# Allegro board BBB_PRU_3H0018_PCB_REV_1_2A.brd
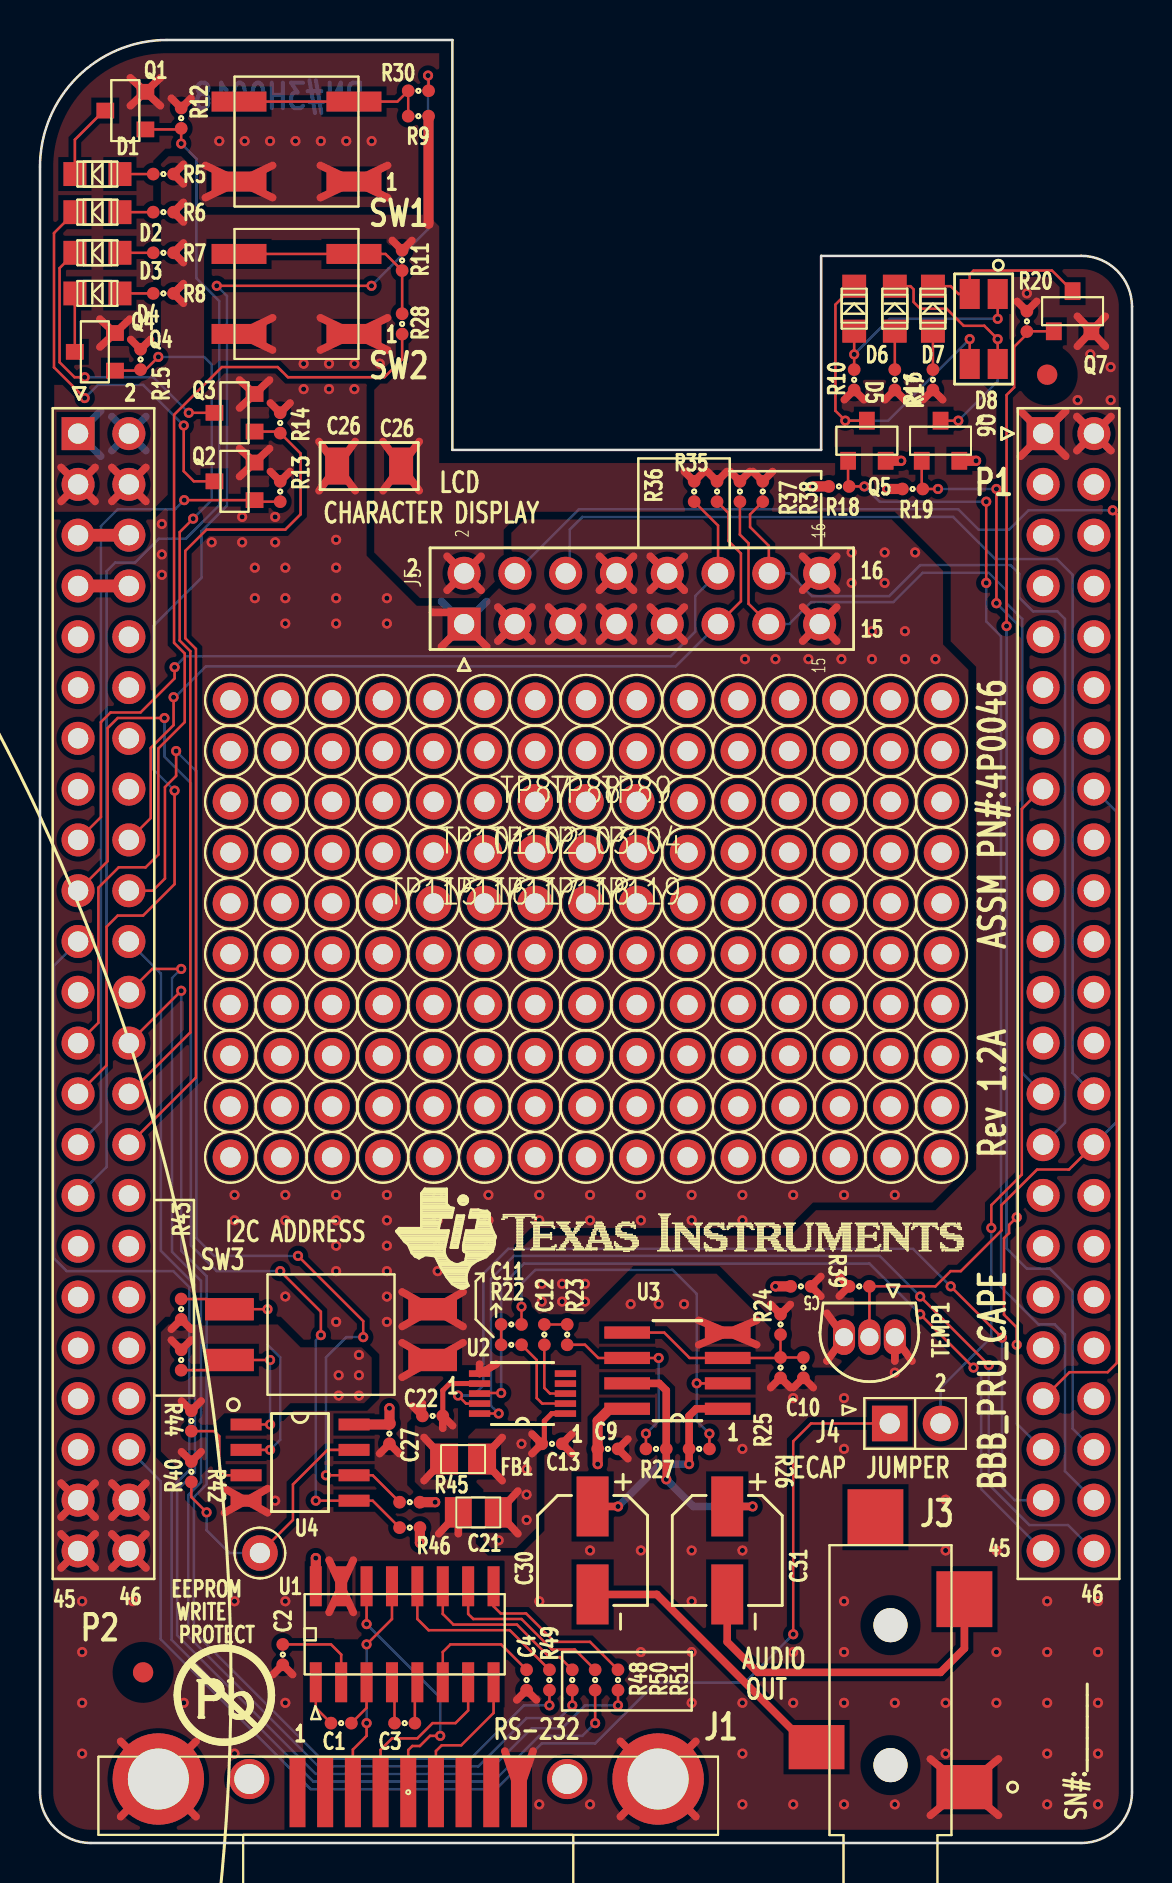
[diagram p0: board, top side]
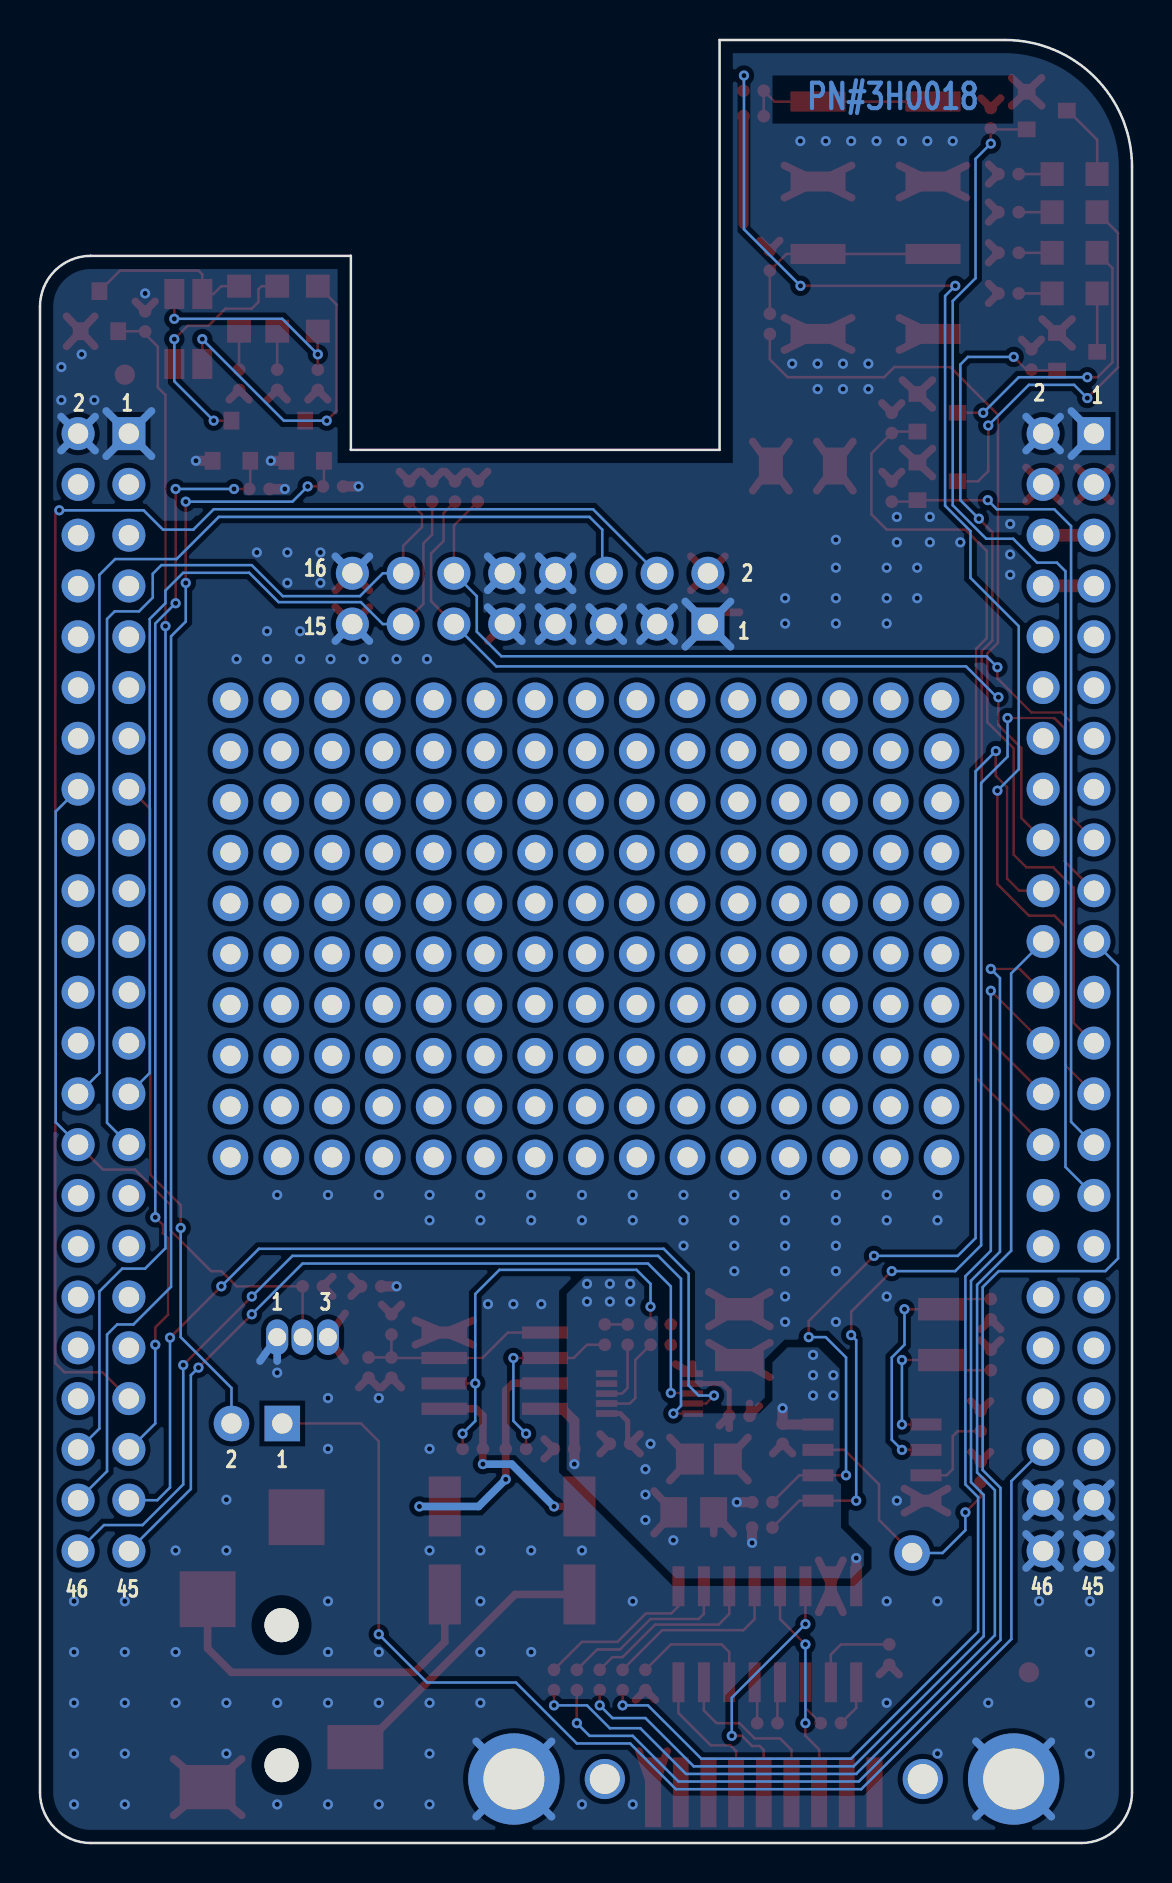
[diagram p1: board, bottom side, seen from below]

Outline 54.61 x 90.17 mm; copper layers: TOP, BOTTOM. Coordinates in mm from the lower left corner of the outline.
Outline path: 0,83.82 arc(1.86,88.31) 6.35,90.17 20.62,90.17 20.62,69.67 39.07,69.67 39.07,79.38 52.07,79.38 arc(53.87,78.63) 54.61,76.84 54.61,2.54 arc(53.87,0.74) 52.07,0 2.54,0 arc(0.74,0.74) 0,2.54 0,83.82

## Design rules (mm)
net group PWR: nets VCC_3V3_AUDIO VCC_5V
nets with their own width: min track width 0.381; nets N10952938 N10953743 N10962161 N11005950

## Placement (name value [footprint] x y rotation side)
C1  0.1uF  [SM-7351-CAP-0402]  15.06 5.99 0 top
C2  0.1uF  [SM-7351-CAP-0402]  12.14 9.42 270 top
C3  0.1uF  [SM-7351-CAP-0402]  18.24 5.99 0 top
C4  0.1uF  [SM-7351-CAP-0402]  24.33 8.15 270 top
C5  0.1uF  [SM-7351-CAP-0402]  38.05 27.84 180 top
C9  0.1uF  [SM-7351-CAP-0402]  28.4 19.71 0 top
C10  1uF  [SM-7351-CAP-0402]  38.18 23.77 90 top
C11  2.2uF, 10V  [SM-7351-CAP-0402]  23.57 24.92 180 top
C12  2.2uF, 10V  [SM-7351-CAP-0402]  25.22 25.43 90 top
C13  0.1uF  [SM-7351-CAP-0402]  25.6 19.96 0 top
C21  10uF  [SM-7351-CAP-0805]  21.92 16.54 180 top
C22  0.1uF  [SM-7351-CAP-0402]  19.63 21.36 180 top
C26  47uF  [SM-7351-CAP-1206]  16.46 68.86 0 top
C27  0.1uF  [SM-7351-CAP-0402]  17.48 20.47 270 top
C30  100uF, 6.3V  [CAP-ALUM-FS-D5XL5]  27.64 14.63 270 top
C31  100uF, 6.3V  [CAP-ALUM-FS-D5XL5]  34.37 14.63 270 top
D1  Blue LED  [SM_LED_0805]  2.87 83.46 180 top
D2  Green LED  [SM_LED_0805]  2.87 81.56 180 top
D3  Orange LED  [SM_LED_0805]  2.87 79.53 180 top
D4  Red LED  [SM_LED_0805]  2.87 77.5 180 top
D5  Blue LED  [SM_LED_0805]  40.72 76.73 90 top
D6  Green LED  [SM_LED_0805]  42.75 76.73 90 top
D7  Red LED  [SM_LED_0805]  44.65 76.73 90 top
D8  Red_Green_Yellow_LED  [LED-SM1210]  47.19 75.72 270 top
FB1  150OHM800mA  [SM-7351-IND-0805]  21.16 19.2 180 top
J1  Conn_DB9M  [NORCOMP_DB9M_SMD]  18.41 2.54 180 top
J3  3.5mm SJ3524  [SJ3524SMT4PIN]  46.48 2.79 270 top
J4  HEADER 2  [HEADER_2X1]  42.49 20.98 270 top
J5  HEADER 8x2 Female  [HDR2X8-335M]  21.21 60.96 90 top
NOREF  -  []  0 83.82 0 top
NOREF#2  -  []  52.07 0 90 top
NOREF#3  -  []  5.92 3.2 0 top
NOREF#4  -  [unnamed#2]  50.37 73.43 0 top
NOREF#5  -  []  21.98 21.48 0 top
NOREF#6  -  []  2.54 0 90 top
NOREF#7  -  []  20.62 90.17 0 top
NOREF#8  -  []  39.07 79.38 0 top
NOREF#9  -  []  9.22 7.39 0 top
NOREF#10  -  []  1.58 88.01 0 top
NOREF#11  -  []  -47.27 -78.56 0 top
NOREF#12  -  []  54.03 78.45 0 top
NOREF#13  -  [unnamed#2]  5.16 8.53 0 top
NOREF#14  -  []  0 83.82 0 top
P1  MALE HEADER 2x23  [HEADER23X2]  50.16 70.48 270 top
P2  MALE HEADER 2x23  [HEADER23X2]  1.9 70.48 270 top
Q1  BSS138  [SOT23-3]  4.27 86.64 90 top
Q2  BSS138  [SOT23-3]  9.73 68.1 90 top
Q3  BSS138  [SOT23-3]  9.73 71.53 90 top
Q4  BSS138  [SOT23-3]  2.74 74.57 90 top
Q5  BSS138  [SOT23-3]  41.35 70.13 0 top
Q6  BSS138  [SOT23-3]  45.03 70.13 0 top
Q7  BSS138  [SOT23-3]  51.64 76.61 0 top
R5  470  [SM-7351-RES-0402]  6.17 83.46 0 top
R6  68  [SM-7351-RES-0402]  6.17 81.56 0 top
R7  470  [SM-7351-RES-0402]  6.17 79.53 0 top
R8  300  [SM-7351-RES-0402]  6.17 77.5 0 top
R9  100K  [SM-7351-RES-0402]  18.92 86.36 0 top
R10  470  [SM-7351-RES-0402]  40.72 73.18 270 top
R11  100K  [SM-7351-RES-0402]  18.11 79.15 90 top
R12  100K  [SM-7351-RES-0402]  7.06 86.26 270 top
R13  100K  [SM-7351-RES-0402]  12.01 67.59 270 top
R14  100K  [SM-7351-RES-0402]  12.01 71.02 270 top
R15  100K  [SM-7351-RES-0402]  5.03 74.19 270 top
R16  68  [SM-7351-RES-0402]  42.75 73.18 270 top
R17  300  [SM-7351-RES-0402]  44.65 73.18 270 top
R18  100K  [SM-7351-RES-0402]  39.95 67.84 0 top
R19  100K  [SM-7351-RES-0402]  43.64 67.72 0 top
R20  100K  [SM-7351-RES-0402]  49.35 76.1 270 top
R22  3.9K  [SM-7351-RES-0402]  23.57 25.93 180 top
R23  3.9K  [SM-7351-RES-0402]  26.37 25.43 90 top
R24  100K  [SM-7351-RES-0402]  37.03 25.93 90 top
R25  100K  [SM-7351-RES-0402]  37.03 23.77 90 top
R26  1K  [SM-7351-RES-0402]  32.97 19.71 0 top
R27  1K  [SM-7351-RES-0402]  30.81 19.71 0 top
R28  100K  [SM-7351-RES-0402]  18.11 75.97 90 top
R30  100K  [SM-7351-RES-0402]  18.92 87.63 180 top
R35  100K  [SM-7351-RES-0402]  33.86 67.59 90 top
R36  100K  [SM-7351-RES-0402]  32.72 67.59 90 top
R37  100K  [SM-7351-RES-0402]  35 67.59 90 top
R38  100K  [SM-7351-RES-0402]  36.14 67.59 90 top
R39  4.7K  [SM-7351-RES-0402]  40.97 27.84 180 top
R40  100K  [SM-7351-RES-0402]  7.57 18.57 90 top
R42  4.7K  [SM-7351-RES-0402]  7.06 24.16 90 top
R43  4.7K  [SM-7351-RES-0402]  7.06 26.7 270 top
R44  4.7K  [SM-7351-RES-0402]  7.57 21.11 90 top
R45  4.7K  [SM-7351-RES-0402]  18.49 17.04 0 top
R46  4.7K  [SM-7351-RES-0402]  18.49 15.77 0 top
R48  0  [SM-7351-RES-0402]  26.62 8.15 270 top
R49  0  [SM-7351-RES-0402]  25.48 8.15 270 top
R50  0  [SM-7351-RES-0402]  27.76 8.15 270 top
R51  0  [SM-7351-RES-0402]  28.91 8.15 270 top
SW1  B3SL-1002P  [SW_B3SL-1022P]  12.83 85.09 0 top
SW2  B3SL-1002P  [SW_B3SL-1022P]  12.83 77.47 0 top
SW3  SW DIP-2  [SWDIP2_SMD]  18.36 24.16 180 top
TEMP1  MAX31820MCR  [TO-92-3P]  42.75 25.3 180 top
TP50  TP  [TH_TP_5002]  11 14.5 0 top
TP51  TP  [TH_TP_5002]  9.52 57.15 0 top
TP52  TP  [TH_TP_5002]  12.06 57.15 0 top
TP53  TP  [TH_TP_5002]  14.61 57.15 0 top
TP54  TP  [TH_TP_5002]  17.14 57.15 0 top
TP55  TP  [TH_TP_5002]  19.68 57.15 0 top
TP56  TP  [TH_TP_5002]  22.22 57.15 0 top
TP57  TP  [TH_TP_5002]  24.77 57.15 0 top
TP58  TP  [TH_TP_5002]  27.3 57.15 0 top
TP59  TP  [TH_TP_5002]  29.84 57.15 0 top
TP60  TP  [TH_TP_5002]  32.38 57.15 0 top
TP61  TP  [TH_TP_5002]  34.92 57.15 0 top
TP62  TP  [TH_TP_5002]  37.47 57.15 0 top
TP63  TP  [TH_TP_5002]  40 57.15 0 top
TP64  TP  [TH_TP_5002]  42.55 57.15 0 top
TP65  TP  [TH_TP_5002]  45.09 57.15 0 top
TP66  TP  [TH_TP_5002]  9.52 54.61 0 top
TP67  TP  [TH_TP_5002]  12.06 54.61 0 top
TP68  TP  [TH_TP_5002]  14.61 54.61 0 top
TP69  TP  [TH_TP_5002]  17.14 54.61 0 top
TP70  TP  [TH_TP_5002]  19.68 54.61 0 top
TP71  TP  [TH_TP_5002]  22.22 54.61 0 top
TP72  TP  [TH_TP_5002]  24.77 54.61 0 top
TP73  TP  [TH_TP_5002]  27.3 54.61 0 top
TP74  TP  [TH_TP_5002]  29.84 54.61 0 top
TP75  TP  [TH_TP_5002]  32.38 54.61 0 top
TP76  TP  [TH_TP_5002]  34.92 54.61 0 top
TP77  TP  [TH_TP_5002]  37.47 54.61 0 top
TP78  TP  [TH_TP_5002]  40 54.61 0 top
TP79  TP  [TH_TP_5002]  42.55 54.61 0 top
TP80  TP  [TH_TP_5002]  45.09 54.61 0 top
TP81  TP  [TH_TP_5002]  9.52 52.07 0 top
TP82  TP  [TH_TP_5002]  12.06 52.07 0 top
TP83  TP  [TH_TP_5002]  14.61 52.07 0 top
TP84  TP  [TH_TP_5002]  17.14 52.07 0 top
TP85  TP  [TH_TP_5002]  19.68 52.07 0 top
TP86  TP  [TH_TP_5002]  22.22 52.07 0 top
TP87  TP  [TH_TP_5002]  24.77 52.07 0 top
TP88  TP  [TH_TP_5002]  27.3 52.07 0 top
TP89  TP  [TH_TP_5002]  29.84 52.07 0 top
TP90  TP  [TH_TP_5002]  32.38 52.07 0 top
TP91  TP  [TH_TP_5002]  34.92 52.07 0 top
TP92  TP  [TH_TP_5002]  37.47 52.07 0 top
TP93  TP  [TH_TP_5002]  40 52.07 0 top
TP94  TP  [TH_TP_5002]  42.55 52.07 0 top
TP95  TP  [TH_TP_5002]  45.09 52.07 0 top
TP96  TP  [TH_TP_5002]  9.52 49.53 0 top
TP97  TP  [TH_TP_5002]  12.06 49.53 0 top
TP98  TP  [TH_TP_5002]  14.61 49.53 0 top
TP99  TP  [TH_TP_5002]  17.14 49.53 0 top
TP100  TP  [TH_TP_5002]  19.68 49.53 0 top
TP101  TP  [TH_TP_5002]  22.22 49.53 0 top
TP102  TP  [TH_TP_5002]  24.77 49.53 0 top
TP103  TP  [TH_TP_5002]  27.3 49.53 0 top
TP104  TP  [TH_TP_5002]  29.84 49.53 0 top
TP105  TP  [TH_TP_5002]  32.38 49.53 0 top
TP106  TP  [TH_TP_5002]  34.92 49.53 0 top
TP107  TP  [TH_TP_5002]  37.47 49.53 0 top
TP108  TP  [TH_TP_5002]  40 49.53 0 top
TP109  TP  [TH_TP_5002]  42.55 49.53 0 top
TP110  TP  [TH_TP_5002]  45.09 49.53 0 top
TP111  TP  [TH_TP_5002]  9.52 46.99 0 top
TP112  TP  [TH_TP_5002]  12.06 46.99 0 top
TP113  TP  [TH_TP_5002]  14.61 46.99 0 top
TP114  TP  [TH_TP_5002]  17.14 46.99 0 top
TP115  TP  [TH_TP_5002]  19.68 46.99 0 top
TP116  TP  [TH_TP_5002]  22.22 46.99 0 top
TP117  TP  [TH_TP_5002]  24.77 46.99 0 top
TP118  TP  [TH_TP_5002]  27.3 46.99 0 top
TP119  TP  [TH_TP_5002]  29.84 46.99 0 top
TP120  TP  [TH_TP_5002]  32.38 46.99 0 top
TP121  TP  [TH_TP_5002]  34.92 46.99 0 top
TP122  TP  [TH_TP_5002]  37.47 46.99 0 top
TP123  TP  [TH_TP_5002]  40 46.99 0 top
TP124  TP  [TH_TP_5002]  42.55 46.99 0 top
TP125  TP  [TH_TP_5002]  45.09 46.99 0 top
TP126  TP  [TH_TP_5002]  9.52 44.45 0 top
TP127  TP  [TH_TP_5002]  12.06 44.45 0 top
TP128  TP  [TH_TP_5002]  14.61 44.45 0 top
TP129  TP  [TH_TP_5002]  17.14 44.45 0 top
TP130  TP  [TH_TP_5002]  19.68 44.45 0 top
TP131  TP  [TH_TP_5002]  22.22 44.45 0 top
TP132  TP  [TH_TP_5002]  24.77 44.45 0 top
TP133  TP  [TH_TP_5002]  27.3 44.45 0 top
TP134  TP  [TH_TP_5002]  29.84 44.45 0 top
TP135  TP  [TH_TP_5002]  32.38 44.45 0 top
TP136  TP  [TH_TP_5002]  34.92 44.45 0 top
TP137  TP  [TH_TP_5002]  37.47 44.45 0 top
TP138  TP  [TH_TP_5002]  40 44.45 0 top
TP139  TP  [TH_TP_5002]  42.55 44.45 0 top
TP140  TP  [TH_TP_5002]  45.09 44.45 0 top
TP141  TP  [TH_TP_5002]  9.52 41.91 0 top
TP142  TP  [TH_TP_5002]  12.06 41.91 0 top
TP143  TP  [TH_TP_5002]  14.61 41.91 0 top
TP144  TP  [TH_TP_5002]  17.14 41.91 0 top
TP145  TP  [TH_TP_5002]  19.68 41.91 0 top
TP146  TP  [TH_TP_5002]  22.22 41.91 0 top
TP147  TP  [TH_TP_5002]  24.77 41.91 0 top
TP148  TP  [TH_TP_5002]  27.3 41.91 0 top
TP149  TP  [TH_TP_5002]  29.84 41.91 0 top
TP150  TP  [TH_TP_5002]  32.38 41.91 0 top
TP151  TP  [TH_TP_5002]  34.92 41.91 0 top
TP152  TP  [TH_TP_5002]  37.47 41.91 0 top
TP153  TP  [TH_TP_5002]  40 41.91 0 top
TP154  TP  [TH_TP_5002]  42.55 41.91 0 top
TP155  TP  [TH_TP_5002]  45.09 41.91 0 top
TP156  TP  [TH_TP_5002]  9.52 39.37 0 top
TP157  TP  [TH_TP_5002]  12.06 39.37 0 top
TP158  TP  [TH_TP_5002]  14.61 39.37 0 top
TP159  TP  [TH_TP_5002]  17.14 39.37 0 top
TP160  TP  [TH_TP_5002]  19.68 39.37 0 top
TP161  TP  [TH_TP_5002]  22.22 39.37 0 top
TP162  TP  [TH_TP_5002]  24.77 39.37 0 top
TP163  TP  [TH_TP_5002]  27.3 39.37 0 top
TP164  TP  [TH_TP_5002]  29.84 39.37 0 top
TP165  TP  [TH_TP_5002]  32.38 39.37 0 top
TP166  TP  [TH_TP_5002]  34.92 39.37 0 top
TP167  TP  [TH_TP_5002]  37.47 39.37 0 top
TP168  TP  [TH_TP_5002]  40 39.37 0 top
TP169  TP  [TH_TP_5002]  42.55 39.37 0 top
TP170  TP  [TH_TP_5002]  45.09 39.37 0 top
TP171  TP  [TH_TP_5002]  9.52 36.83 0 top
TP172  TP  [TH_TP_5002]  12.06 36.83 0 top
TP173  TP  [TH_TP_5002]  14.61 36.83 0 top
TP174  TP  [TH_TP_5002]  17.14 36.83 0 top
TP175  TP  [TH_TP_5002]  19.68 36.83 0 top
TP176  TP  [TH_TP_5002]  22.22 36.83 0 top
TP177  TP  [TH_TP_5002]  24.77 36.83 0 top
TP178  TP  [TH_TP_5002]  27.3 36.83 0 top
TP179  TP  [TH_TP_5002]  29.84 36.83 0 top
TP180  TP  [TH_TP_5002]  32.38 36.83 0 top
TP181  TP  [TH_TP_5002]  34.92 36.83 0 top
TP182  TP  [TH_TP_5002]  37.47 36.83 0 top
TP183  TP  [TH_TP_5002]  40 36.83 0 top
TP184  TP  [TH_TP_5002]  42.55 36.83 0 top
TP185  TP  [TH_TP_5002]  45.09 36.83 0 top
TP186  TP  [TH_TP_5002]  9.52 34.29 0 top
TP187  TP  [TH_TP_5002]  12.06 34.29 0 top
TP188  TP  [TH_TP_5002]  14.61 34.29 0 top
TP189  TP  [TH_TP_5002]  17.14 34.29 0 top
TP190  TP  [TH_TP_5002]  19.68 34.29 0 top
TP191  TP  [TH_TP_5002]  22.22 34.29 0 top
TP192  TP  [TH_TP_5002]  24.77 34.29 0 top
TP193  TP  [TH_TP_5002]  27.3 34.29 0 top
TP194  TP  [TH_TP_5002]  29.84 34.29 0 top
TP195  TP  [TH_TP_5002]  32.38 34.29 0 top
TP196  TP  [TH_TP_5002]  34.92 34.29 0 top
TP197  TP  [TH_TP_5002]  37.47 34.29 0 top
TP198  TP  [TH_TP_5002]  40 34.29 0 top
TP199  TP  [TH_TP_5002]  42.55 34.29 0 top
TP200  TP  [TH_TP_5002]  45.09 34.29 0 top
U1  MAX3232E  [U_16_D]  18.24 10.44 0 top
U2  DAC082S085  [MUB10A-L]  24.13 22.48 180 top
U3  LM4808  [M08A-M]  31.88 23.62 180 top
U4  CAT24C256W  [SOIC8_MC]  13 19.02 0 top

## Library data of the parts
C1 C3 C9 C13 C22 C27 = 1C_0.1uFCapacitor16V10%0402
C2 C4 C5 = 1C_0.1uFCapacitor16V10%0402: Tolerance: TOLERANCE; User Part Number: USERPART#
C10 = 1C_1uFCapacitor10V10%0402
C11 C12 = 1C_2.2uFCapacitor10V20%smd0402
C21 = 1C_10uFCapacitor16V10%0805
C26 = 1C_47uFCapacitor16V20%1206
C30 C31 = 1C_100uFCapacitor6.3V20%ElecAl
D1 D5 = 1F_LED_Blue
D2 D6 = 1F_LED_Green
D3 = 1F_LED_Orange
D4 D7 = 1F_LED_Red
D8 = 1F_LED_Tricolor_RedGreenYellow
FB1 = 1L_FerBead_180ohm200mA
J1 = Conn_DSUB9M
J3 = 2C_Conn_3.5mm_SJ3524SMT
J4 = 2H_Header_2x1
J5 = 2H_Header8x2pin_female
P1 P2 = HDR_46_F_2_0.1_0.1
Q1-Q7 = 1Q_MOSFET_NChan_BSS138
R5 R7 R10 = 1R_470OhmResistor1/16W1%0402
R6 R16 = 1R_68ohm1/16W5%smd0402
R8 R17 = 1R_300ohm1/16W5%smd0402
R9 R11-R15 R18-R20 R24 R25 R28 R30 R35-R38 R40 = 1R_100KOhmResistor1/16W0402
R22 R23 = 1R_3.9Kohm1/16W1%smd0402
R26 R27 = 1R_1KOhmResistor1/16W0402
R39 R42-R46 = 1R_4.7KOhmResistor1/16W0402
R48-R51 = 1R_ZeroOhmResistor1/16W0402
SW1 SW2 = 2W_Switch_PushbuttonsmdNOtall
SW3 = SW DIP-2
TEMP1 = 1A_MAX31820MCR
TP50-TP200 = 2H_TestPointThroughHole
U1 = 1A_MAX3232E
U2 = 1A_DAC082S085
U3 = 1A_LM4808
U4 = 1A_CAT24C256W

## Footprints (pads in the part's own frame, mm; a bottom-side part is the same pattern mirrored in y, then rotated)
CAP-ALUM-FS-D5XL5
  rect 3x1.6 smd: 1(-2.2,0) 2(2.2,0)
HDR2X8-335M
  rect 1.651x1.651 hole 1.016: 1(0,0)
  round 1.651 hole 1.016: 2(2.54,0) 3(0,-2.54) 4(2.54,-2.54) 5(0,-5.08) 6(2.54,-5.08) 7(0,-7.62) 8(2.54,-7.62) 9(0,-10.16) 10(2.54,-10.16) 11(0,-12.7) 12(2.54,-12.7) 13(0,-15.24) 14(2.54,-15.24) 15(0,-17.78) 16(2.54,-17.78)
HEADER23X2
  rect 1.651x1.651 hole 1.016: 1(0,0)
  round 1.651 hole 1.016: 2(0,2.54) 3(2.54,0) 4(2.54,2.54) 5(5.08,0) 6(5.08,2.54) 7(7.62,0) 8(7.62,2.54) 9(10.16,0) 10(10.16,2.54) 11(12.7,0) 12(12.7,2.54) 13(15.24,0) 14(15.24,2.54) 15(17.78,0) 16(17.78,2.54) 17(20.32,0) 18(20.32,2.54) 19(22.86,0) 20(22.86,2.54) 21(25.4,0) 22(25.4,2.54) 23(27.94,0) 24(27.94,2.54) 25(30.48,0) 26(30.48,2.54) 27(33.02,0) 28(33.02,2.54) 29(35.56,0) 30(35.56,2.54) 31(38.1,0) 32(38.1,2.54) 33(40.64,0) 34(40.64,2.54) 35(43.18,0) 36(43.18,2.54) 37(45.72,0) 38(45.72,2.54) 39(48.26,0) 40(48.26,2.54) 41(50.8,0) 42(50.8,2.54) 43(53.34,0) 44(53.34,2.54) 45(55.88,0) 46(55.88,2.54)
HEADER_2X1
  rect 1.778x1.778 hole 1.016: 1(0,0)
  round 1.778 hole 1.016: 2(0,2.54)
LED-SM1210
  rect 1.5x1 smd: 1(-1.75,0.7) 2(-1.75,-0.7) 3(1.75,0.7) 4(1.75,-0.7)
M08A-M
  rect 2.286x0.61 smd: 1(-2.515,1.905) 2(-2.515,0.635) 3(-2.515,-0.635) 4(-2.515,-1.905) 5(2.515,-1.905) 6(2.515,-0.635) 7(2.515,0.635) 8(2.515,1.905)
MUB10A-L
  rect 1.067x0.33 smd: 1(-2.146,1) 2(-2.146,0.5) 3(-2.146,0) 4(-2.146,-0.5) 5(-2.146,-1) 6(2.146,-1) 7(2.146,-0.5) 8(2.146,0) 9(2.146,0.5) 10(2.146,1)
NORCOMP_DB9M_SMD
  round 2.007 hole 1.499 unplated: (-7.95,-0.66) (7.95,-0.66)
  rect 0.8x3.5 smd: 1(5.537,0) 2(2.769,0) 3(0,0) 4(-2.769,0) 5(-5.537,0) 6(4.153,0) 7(1.384,0) 8(-1.384,0) 9(-4.153,0)
  round 4.572 hole 3.048: 10(-12.497,-0.66) 11(12.497,-0.66)
SJ3524SMT4PIN
  round 1.702 hole 1.702 unplated: (-8.1,-3.95) (-1.1,-3.95)
  rect 2.21x2.794 smd: 1(0,-0.253) 3(-2,-7.647)
  rect 2.794x2.794 smd: 2(-9.4,-0.253) 10(-13.5,-4.703)
SM-7351-CAP-0402
  round 0.635 smd: 1(-0.508,0) 2(0.508,0)
SM-7351-CAP-0805
  rect 1.346x1.524 smd: 1(-1,0) 2(1,0)
SM-7351-CAP-1206
  rect 1.2x1.85 smd: 1(1.6,0) 2(-1.6,0)
SM-7351-IND-0805
  rect 1.397x1.549 smd: 1(-0.95,0) 2(0.95,0)
SM-7351-RES-0402
  round 0.635 smd: 1(-0.508,0) 2(0.508,0)
SM_LED_0805
  rect 1.15x1.194 smd: 1(1.125,0) 2(-1.125,0)
SOIC8_MC
  rect 1.55x0.6 smd: 1(-2.7,1.905) 2(-2.7,0.635) 3(-2.7,-0.635) 4(-2.7,-1.905) 5(2.7,-1.905) 6(2.7,-0.635) 7(2.7,0.635) 8(2.7,1.905)
SOT23-3
  rect 0.787x0.889 smd: D(0,1.003) G(-0.94,-1.003) S(0.94,-1.003)
SW_B3SL-1022P
  rect 2.75x1 smd: 1(2.875,-2) 2(-2.875,-2) 3(2.875,2) 4(-2.875,2)
SWDIP2_SMD
  rect 2.438x1.118 smd: 1(-1.27,0) 2(-1.27,-2.54) 3(8.89,-2.54) 4(8.89,0)
TH_TP_5002
  round 1.778 hole 1.016: 1(0,0)
TO-92-3P
  oval 1.103x1.778 hole 0.9: 1(0,0) 2(1.27,0) 3(2.54,0)
U_16_D
  rect 0.6x2 smd: 1(-4.445,-2.4) 2(-3.175,-2.4) 3(-1.905,-2.4) 4(-0.635,-2.4) 5(0.635,-2.4) 6(1.905,-2.4) 7(3.175,-2.4) 8(4.445,-2.4) 9(4.445,2.4) 10(3.175,2.4) 11(1.905,2.4) 12(0.635,2.4) 13(-0.635,2.4) 14(-1.905,2.4) 15(-3.175,2.4) 16(-4.445,2.4)
unnamed#2
  round 1.016 smd: 1(0,0)

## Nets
DGND: C2.2 C4.2 C5.2 C9.2 C10.1 C13.2 C21.2 C22.2 C26.2 C27.2 J1.5 J1.10 J1.11 J3.1(P1) J5.1 J5.3 J5.5 J5.7 J5.8 J5.9 J5.10 J5.15 J5.16 P1.1 P1.2(26) P2.1 P2.2(26) P2.43(22) P2.44(47) P2.45(23) P2.46(48) Q1.S(SOURCE) Q2.S(SOURCE) Q3.S(SOURCE) Q4.S(SOURCE) Q5.S(SOURCE) Q6.S(SOURCE) Q7.S(SOURCE) R12.1(P1) R13.1(P1) R14.1(P1) R15.1(P1) R18.1(P1) R19.1(P1) R20.1(P1) R25.1(P1) SW1.1 SW1.2 SW2.1 SW2.2 SW3.1(A1) SW3.2(A2) TEMP1.1(GND) U1.15(GND) U2.6(GND) U3.4(GND) U4.4(VSS)
VCC_3V3_AUDIO: C22.1 FB1.2 U2.7(VREFIN)
VCC_3V3C: C5.1 C9.1 C13.1 C21.1 C26.1 C27.1 FB1.1 J5.2 P2.3(2) P2.4(27) R5.2(P2) R6.2(P2) R7.2(P2) R8.2(P2) R9.2(P2) R10.2(P2) R11.2(P2) R16.2(P2) R17.2(P2) R24.2(P2) R35.2(P2) R36.2(P2) R37.2(P2) R38.2(P2) R39.2(P2) R40.2(P2) R42.2(P2) R43.2(P2) R44.2(P2) R45.2(P2) R46.2(P2) TEMP1.3(VDD) U1.16(VCC) U2.1(VA) U3.8(VDD) U4.8(VCC)
VCC_5V: P2.5(3) P2.6(28)
I2C2_SCL: P2.20(35) R45.1(P1) U4.6(SCL)
I2C2_SDA: P2.19(10) R46.1(P1) U4.5(SDA)
PR1_ECAP0_IN_PWM0_OUT: J4.1 P2.42(46)
PR1_PRU0_GPI5: P2.27(14) R30.1(P1)
PR1_PRU0_GPI7: P2.25(13) R28.1(P1)
PR1_PRU0_GPI14: P1.16(33) P1.30(40) R39.1(P1) TEMP1.2(DQ)
PR1_PRU0_GPI15: J4.2 P1.15(8)
PR1_PRU0_GPO0: P2.31(16) Q1.G(GATE) R12.2(P2)
PR1_PRU0_GPO1: P2.29(15) Q2.G(GATE) R13.2(P2)
PR1_PRU0_GPO2: P2.30(40) Q3.G(GATE) R14.2(P2)
PR1_PRU0_GPO3: P2.28(39) Q4.G(GATE) R15.2(P2)
PR1_PRU1_GPO0: P1.45(23) U2.8(DIN)
PR1_PRU1_GPO1: P1.46(48) U2.10(SCLK)
PR1_PRU1_GPO2: P1.43(22) U2.9(SYNCN)
PR1_PRU1_GPO3: P1.44(47) Q5.G(GATE) R18.2(P2)
PR1_PRU1_GPO4: P1.41(21) Q6.G(GATE) R19.2(P2)
PR1_PRU1_GPO5: P1.42(46) Q7.G(GATE) R20.2(P2)
PR1_PRU_EDIO_DATA_OUT0: J5.11 P2.18(34) R35.1(P1)
PR1_PRU_EDIO_DATA_OUT1: J5.12 P2.17(9) R36.1(P1)
PR1_PRU_EDIO_DATA_OUT2: J5.13 P1.27(14) R37.1(P1)
PR1_PRU_EDIO_DATA_OUT3: J5.14 P1.29(15) R38.1(P1)
PR1_PRU_EDIO_DATA_OUT4: J5.6 P1.28(39)
PR1_PRU_EDIO_DATA_OUT6: J5.4 P1.39(20)
PR1_UART0_CTS: P2.22(36) R51.2(P2)
PR1_UART0_RTS: P2.21(11) R50.2(P2)
PR1_UART0_RXD: P2.26(38) R49.2(P2)
PR1_UART0_TXD: P2.24(37) R48.2(P2)
SYS_5V: P2.7(4) P2.8(29)
N10940793: J1.3 U1.14(DOUT1)
N10940805: J1.7 U1.7(DOUT2)
N10940817: J1.2 U1.13(RIN1)
N10940821: J1.8 U1.8(RIN2)
N10940859: C2.1 U1.2(V+)
N10940889: C4.1 U1.6(V-)
N10940931: C1.1 U1.1(C1+)
N10940935: C1.2 U1.3(C1-)
N10940955: C3.1 U1.4(C2+)
N10940959: C3.2 U1.5(C2-)
N10941007: R51.1(P1) U1.9(ROUT2)
N10941037: R48.1(P1) U1.11(DIN1)
N10941057: R50.1(P1) U1.10(DIN2)
N10941079: R49.1(P1) U1.12(ROUT1)
N10944684: D1.1(CATHODE) Q1.D(DRAIN)
N10944706: D2.1(CATHODE) Q2.D(DRAIN)
N10944710: D3.1(CATHODE) Q3.D(DRAIN)
N10944714: D4.1(CATHODE) Q4.D(DRAIN)
N10944926: R9.1(P1) R30.2(P2) SW1.3 SW1.4
N10945010: R11.1(P1) R28.2(P2) SW2.3 SW2.4
N10952704: R23.1(P1) R27.1(P1) U3.6(INB-)
N10952708: R22.1(P1) R26.2(P2) U3.2(INA-)
N10952712: C11.2 R22.2(P2)
N10952716: C11.1 U2.2(VOUTA)
N10952728: C12.2 R23.2(P2)
N10952732: C12.1 U2.3(VOUTB)
N10952860: C10.2 R24.1(P1) R25.2(P2) U3.3(INA+) U3.5(INB+)
N10952938: C30.1(POS) R26.1(P1) U3.1(OUTA)
N10953743: C31.2(NEG) J3.2(P2)
N10962161: C31.1(POS) R27.2(P2) U3.7(OUTB)
N10987134: R42.1(P1) SW3.4(B1) U4.1(A0)
N10987138: R43.1(P1) SW3.3(B2) U4.2(A1)
N10987943: R40.1(P1) TP50.1 U4.7(WP)
N10988256: R44.1(P1) U4.3(A2)
N11005950: C30.2(NEG) J3.3(P3)
N11019823: D5.2(ANODE) D8.1(A) R10.1(P1)
N11021666: D6.1(CATHODE) D8.3(G) Q6.D(DRAIN)
N11021673: D7.1(CATHODE) D8.2(R) Q7.D(DRAIN)
N11030938: D5.1(CATHODE) D8.4(Y) Q5.D(DRAIN)
N109444080: D1.2(ANODE) R5.1(P1)
N109444240: D2.2(ANODE) R6.1(P1)
N109444400: D3.2(ANODE) R7.1(P1)
N109444560: D4.2(ANODE) R8.1(P1)
N110315370: D6.2(ANODE) R16.1(P1)
N110319930: D7.2(ANODE) R17.1(P1)

Pads without a net: J1 1 4 6 9; J3 10; NOREF#4 1; NOREF#13 1; P1 3 4 5 6 7 8 9 10 11 12 13 14 17 18 19 20 21 22 23 24 25 26 31 32 33 34 35 36 37 38 40; P2 9 10 11 12 13 14 15 16 23 32 33 34 35 36 37 38 39 40 41; TP51 1; TP52 1; TP53 1; TP54 1; TP55 1; TP56 1; TP57 1; TP58 1; TP59 1; TP60 1; TP61 1; TP62 1; TP63 1; TP64 1; TP65 1; TP66 1; TP67 1; TP68 1; TP69 1; TP70 1; TP71 1; TP72 1; TP73 1; TP74 1; TP75 1; TP76 1; TP77 1; TP78 1; TP79 1; TP80 1; TP81 1; TP82 1; TP83 1; TP84 1; TP85 1; TP86 1; TP87 1; TP88 1; TP89 1; TP90 1; TP91 1; TP92 1; TP93 1; TP94 1; TP95 1; TP96 1; TP97 1; TP98 1; TP99 1; TP100 1; TP101 1; TP102 1; TP103 1; TP104 1; TP105 1; TP106 1; TP107 1; TP108 1; TP109 1; TP110 1; TP111 1; TP112 1; TP113 1; TP114 1; TP115 1; TP116 1; TP117 1; TP118 1; TP119 1; TP120 1; TP121 1; TP122 1; TP123 1; TP124 1; TP125 1; TP126 1; TP127 1; TP128 1; TP129 1; TP130 1; TP131 1; TP132 1; TP133 1; TP134 1; TP135 1; TP136 1; TP137 1; TP138 1; TP139 1; TP140 1; TP141 1; TP142 1; TP143 1; TP144 1; TP145 1; TP146 1; TP147 1; TP148 1; TP149 1; TP150 1; TP151 1; TP152 1; TP153 1; TP154 1; TP155 1; TP156 1; TP157 1; TP158 1; TP159 1; TP160 1; TP161 1; TP162 1; TP163 1; TP164 1; TP165 1; TP166 1; TP167 1; TP168 1; TP169 1; TP170 1; TP171 1; TP172 1; TP173 1; TP174 1; TP175 1; TP176 1; TP177 1; TP178 1; TP179 1; TP180 1; TP181 1; TP182 1; TP183 1; TP184 1; TP185 1; TP186 1; TP187 1; TP188 1; TP189 1; TP190 1; TP191 1; TP192 1; TP193 1; TP194 1; TP195 1; TP196 1; TP197 1; TP198 1; TP199 1; TP200 1; U2 4 5

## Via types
v1: diameter 0.508, hole 0.254, TOP to BOTTOM, 246 vias

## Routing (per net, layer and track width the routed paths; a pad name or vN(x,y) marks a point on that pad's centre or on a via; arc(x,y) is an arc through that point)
DGND: length 317.1
  TOP w0.381: 19.63,26.7 21.16,27.56 ; 19.63,26.7 18.11,25.83 ; 19.63,26.7 21.16,25.83 ; 19.63,26.7 18.11,27.56 ; 30.52,61.81 J5.9 ; J5.9 30.52,60.11 ; J5.9 32.22,60.11 ; J5.9 32.22,61.81 ; 12.51,68.59 12.01,68.1 11.52,68.59 ; J1.10 32.79,1.32 ; J1.10 29.03,1.32 ; J1.10 29.03,5.08 ; J1.10 32.79,5.08 ; 22.9,61.81 J5.3 ; J5.3 22.9,60.11 ; J5.3 24.6,61.81 ; J5.3 24.6,60.11 ; 20.92,15.47 C21.2 19.94,15.47 ; C26.2 15.76,67.63 ; C26.2 13.95,70.09 ; C26.2 13.95,67.63 ; C26.2 15.76,70.09 ; P2.45 2.76,13.75 ; P2.45 1.05,15.46 ; P2.45 1.05,13.75 ; P2.45 2.76,15.46 ; 18.11,25.02 SW3.1 ; SW3.1 21.16,25.02 ; SW3.1 18.11,23.29 ; 42.75,24.1 TEMP1.1 43.61,24.1 ; SW2.1 17.38,74.66 ; SW2.1 14.02,74.66 ; SW2.1 17.38,76.28 ; SW2.1 14.02,76.28 ; 3.59,13.75 P2.46 ; P2.46 5.3,13.75 ; P2.46 5.3,15.46 ; P2.46 3.59,15.46 ; 9.98,71.77 Q3.S ; Q3.S 11.48,73.17 ; Q3.S 9.98,73.17 ; 14.02,83.9 SW1.1 ; SW1.1 17.38,82.28 ; SW1.1 14.02,82.28 ; SW1.1 17.38,83.9 ; 51.88,76.35 Q7.S ; Q7.S 51.88,74.85 ; Q7.S 53.28,76.35 ; Q7.S 53.28,74.85 ; 25.44,60.11 J5.5 ; J5.5 27.14,60.11 ; J5.5 27.14,61.81 ; J5.5 25.44,61.81 ; J1.11 7.8,5.08 ; J1.11 7.8,1.32 ; J1.11 4.04,5.08 ; J1.11 4.04,1.32 ; 3,74.82 Q4.S ; Q4.S 3,76.21 ; Q4.S 4.5,76.21 ; P1.1 51.3,69.35 ; P1.1 51.3,71.62 ; P1.1 49.03,71.62 ; P1.1 49.03,69.35 ; 38.14,60.11 J5.15 ; J5.15 39.84,61.81 ; J5.15 38.14,61.81 ; J5.15 39.84,60.11 ; 48.86,77.1 R20.1 49.84,77.1 ; P2.44 5.3,18 ; P2.44 5.3,16.29 ; P2.44 3.59,18 ; P2.44 3.59,16.29 ; 12.63,8.42 C2.2 11.65,8.42 ; 23.25,4.6 J1.5 24.66,4.6 ; J5.10 32.22,64.35 ; J5.10 32.22,62.65 ; J5.10 30.52,62.65 ; J5.10 30.52,64.35 ; 9.22,17.72 U4.4 ; U4.4 9.22,16.51 ; U4.4 11.39,16.51 ; U4.4 11.39,17.72 ; 27.98,64.35 J5.8 ; J5.8 29.68,62.65 ; J5.8 29.68,64.35 ; J5.8 27.98,62.65 ; 11.52,72.02 R14.1 12.51,72.02 ; 21.98,23.95 U2.6 22.82,23.95 ; 4.52,86.88 Q1.S ; Q1.S 4.52,88.28 ; Q1.S 6.02,88.28 ; Q1.S 6.02,86.88 ; SW1.2 11.63,82.28 ; SW1.2 8.27,83.9 ; SW1.2 8.27,82.28 ; SW1.2 11.63,83.9 ; J5.1 22.34,59.83 ; J5.1 20.08,59.83 ; J5.1 20.63,61.54 19.64,61.54 19.63,61.55 ; 14.46,11.53 U1.15 ; U1.15 15.67,14.14 ; U1.15 14.46,14.14 ; U1.15 15.67,11.53 ; 38.14,64.35 J5.16 ; J5.16 39.84,64.35 ; J5.16 39.84,62.65 ; J5.16 38.14,62.65 ; 37.52,22.78 R25.1 36.54,22.78 ; J3.1 47.93,4.2 ; J3.1 44.53,1.38 ; J3.1 47.93,1.38 ; J3.1 44.53,4.2 ; 19.13,21.98 C22.2 18.63,21.85 ; 1.05,18 P2.43 ; P2.43 1.05,16.29 ; P2.43 2.76,16.29 ; P2.43 2.76,18 ; 27.98,60.11 J5.7 ; J5.7 27.98,61.81 ; J5.7 29.68,61.81 ; J5.7 29.68,60.11 ; P1.2 53.56,69.63 ; P1.2 51.85,71.34 ; P1.2 51.85,69.63 ; P1.2 53.56,71.34 ; 17.97,19.47 C27.2 16.98,19.47 ; 26.6,19.47 C13.2 26.6,20.46 ; 11.63,76.28 SW2.2 11.63,74.66 ; 29.4,19.22 C9.2 29.4,20.2 ; 37.68,22.78 C10.1 38.67,22.78 ; 9.98,69.74 Q2.S ; Q2.S 9.98,68.34 ; Q2.S 11.48,69.74 ; 7.55,87.26 R12.1 6.57,87.26 ; 32.94,24.92 U3.4 ; U3.4 35.84,26.14 ; U3.4 35.84,24.92 ; U3.4 32.94,26.14 ; 24.82,7.15 C4.2 23.84,7.15 ; 4.54,75.19 R15.1 5.52,75.19
  TOP w0.508: C5.2 v1(36.78,27.84) ; Q6.S v1(46.81,69.13) ; R19.1 v1(42.37,67.72) ; R18.1 v1(38.68,67.84) ; Q5.S v1(43.07,69.13)
  BOTTOM w0.381: J5.7 29.68,61.81 ; J5.7 27.98,60.11 ; J5.7 27.98,61.81 ; J5.7 29.68,60.11 ; 1.05,16.29 P2.43 ; P2.43 2.76,16.29 ; P2.43 2.76,18 ; P2.43 1.05,18 ; P2.2 5.3,71.34 ; P2.2 3.59,69.63 ; P2.2 5.3,69.63 ; P2.2 3.59,71.34 ; J5.8 29.68,62.65 ; J5.8 29.68,64.35 ; J5.8 27.98,64.35 ; J5.8 27.98,62.65 ; 22.9,61.81 J5.3 ; J5.3 24.6,61.81 ; J5.3 22.9,60.11 ; J5.3 24.6,60.11 ; P2.46 5.3,13.75 ; P2.46 5.3,15.46 ; P2.46 3.59,15.46 ; P2.46 3.59,13.75 ; 30.52,64.35 J5.10 ; J5.10 32.22,64.35 ; J5.10 32.22,62.65 ; J5.10 30.52,62.65 ; 25.44,61.81 J5.5 ; J5.5 25.44,60.11 ; J5.5 27.14,61.81 ; J5.5 27.14,60.11 ; J1.11 7.8,1.32 ; J1.11 4.04,5.08 ; J1.11 7.8,5.08 ; J1.11 4.04,1.32 ; 29.03,1.32 J1.10 ; J1.10 32.79,1.32 ; J1.10 32.79,5.08 ; J1.10 29.03,5.08 ; P1.2 53.56,71.34 ; P1.2 51.85,71.34 ; P1.2 51.85,69.63 ; P1.2 53.56,69.63 ; 3.59,16.29 P2.44 ; P2.44 5.3,16.29 ; P2.44 5.3,18 ; P2.44 3.59,18 ; 38.14,60.11 J5.15 39.84,60.11 ; 42.75,24.1 TEMP1.1 43.61,24.1 ; J5.1 22.34,59.83 ; J5.1 20.08,62.09 ; J5.1 20.08,59.83 ; J5.1 22.34,62.09 ; P1.1 51.3,71.62 ; P1.1 49.03,71.62 ; P1.1 49.03,69.35 ; P1.1 51.3,69.35 ; J5.9 32.22,61.81 ; J5.9 30.52,60.11 ; J5.9 30.52,61.81 ; 3.04,71.62 P2.1 3.04,69.35 ; 1.05,13.75 P2.45 ; P2.45 1.05,15.46 ; P2.45 2.76,13.75 ; P2.45 2.76,15.46 ; 38.14,64.35 J5.16 39.84,64.35
  vias: v1(2.11,12.09) v1(2.11,9.55) v1(2.11,7.01) v1(2.11,4.47) v1(4.65,12.09) v1(6.09,65.96) v1(6.09,64.44) v1(6.09,63.42) v1(7.19,7.01) v1(8.59,65.05) v1(8.97,85.12) v1(9.73,32.41) v1(9.73,31.14) v1(9.73,12.09) v1(9.73,4.47) v1(10.11,66.32) v1(10.11,65.05) v1(10.24,85.12) v1(10.74,63.78) v1(10.74,62.26) v1(11.51,85.12) v1(11.76,66.32) v1(11.76,65.05) v1(11.76,17.12) v1(12.27,63.78) v1(12.27,62.26) v1(12.27,60.99) v1(12.27,32.41) v1(12.27,31.14) v1(12.27,27.33) v1(12.27,12.09) v1(12.27,7.01) v1(12.78,85.12) v1(13.18,73.98) v1(13.18,72.71) v1(14.05,85.12) v1(14.45,73.98) v1(14.45,72.71) v1(14.81,65.18) v1(14.81,63.78) v1(14.81,62.26) v1(14.81,60.99) v1(14.81,32.41) v1(14.81,31.14) v1(14.81,29.87) v1(14.81,28.6) v1(14.81,26.06) v1(15.32,85.12) v1(15.72,73.98) v1(15.72,72.71) v1(16.59,85.12) v1(16.99,73.98) v1(17.35,62.26) v1(17.35,60.99) v1(17.35,32.41) v1(17.35,31.14) v1(17.35,29.87) v1(17.35,28.6) v1(17.35,27.33) v1(17.35,26.06) v1(19.89,32.41) v1(19.89,31.14) v1(19.89,29.87) v1(19.89,28.6) v1(22.43,32.41) v1(22.43,31.14) v1(22.43,29.87) v1(24.97,32.41) v1(24.97,31.14) v1(24.97,12.09) v1(24.97,1.93) v1(27.51,32.41) v1(27.51,31.14) v1(27.51,14.63) v1(27.51,1.93) v1(29.54,26.95) v1(30.05,32.41) v1(30.05,31.14) v1(30.05,14.63) v1(30.05,9.55) v1(30.94,26.95) v1(32.21,26.95) v1(32.59,32.41) v1(32.59,31.14) v1(32.59,14.63) v1(32.59,12.09) v1(32.59,9.55) v1(32.59,7.01) v1(35.13,32.41) v1(35.13,31.14) v1(35.13,19.71) v1(35.13,14.63) v1(35.13,7.01) v1(35.13,4.47) v1(35.13,1.93) v1(35.26,59.21) v1(36.78,59.21) v1(37.67,32.41) v1(37.67,22.25) v1(37.67,9.55) v1(37.67,7.01) v1(37.67,1.93) v1(38.43,59.21) v1(40.08,59.21) v1(40.21,32.41) v1(40.21,22.25) v1(40.21,19.71) v1(40.21,12.09) v1(40.21,9.55) v1(40.21,7.01) v1(40.21,1.93) v1(40.59,64.54) v1(40.59,63.02) v1(41.61,60.6) v1(41.61,59.21) v1(42.24,64.54) v1(42.24,63.02) v1(42.75,32.41) v1(42.75,23.52) v1(42.75,7.01) v1(42.75,1.93) v1(43.26,60.6) v1(43.26,59.21) v1(43.76,64.54) v1(44.78,59.21) v1(45.29,17.17) v1(45.29,14.63) v1(45.29,7.01) v1(45.29,4.47) v1(47.83,14.63) v1(47.83,9.55) v1(47.83,7.01) v1(49.35,77.5) v1(50.37,12.09) v1(50.37,9.55) v1(50.37,7.01) v1(50.37,4.47) v1(50.37,1.93) v1(51.89,72.16) v1(52.53,74.45) v1(52.91,12.09) v1(52.91,9.55) v1(52.91,7.01) v1(52.91,4.47) v1(52.91,1.93) v1(53.54,73.81) v1(53.54,72.16)
VCC_3V3_AUDIO: length 7.5
  TOP w0.254: C22.1 20.14,22.63 20.49,22.98 U2.7
  TOP w0.381: 19.2,18.12 FB1.2 19.2,20.28 ; 20.14,20.74 C22.1 20.63,20.87
VCC_3V3C: length 74.3
  TOP w0.254: C13.1 25.22,20.09 25.22,21.11 25.59,21.48 U2.1
  TOP w0.381: 39.05,27.35 C5.1 39.05,28.33 ; 6.57,25.15 7.06,24.66 7.55,25.15 ; 24.6,19.47 C13.1 24.6,20.46 ; 17.62,80.15 R11.2 18.6,80.15 ; 35.65,68.59 36.14,68.1 36.64,68.59 ; 7.08,19.57 R40.2 8.06,19.57 ; J5.2 22.06,62.65 ; J5.2 22.06,64.35 ; J5.2 20.36,64.35 ; J5.2 20.36,62.65 ; P2.3 2.76,67.09 ; P2.3 1.05,67.09 ; P2.3 1.05,68.8 ; P2.3 2.76,68.8 ; 7.17,80.02 R7.2 7.17,79.04 ; C26.1 18.96,67.63 ; C26.1 18.96,70.09 ; C26.1 17.15,70.09 ; C26.1 17.15,67.63 ; 36.54,26.93 R24.2 37.52,26.93 ; 23.9,15.47 C21.1 23.9,17.6 ; 45.14,72.18 44.65,72.67 44.16,72.18 ; 7.17,82.05 R6.2 7.17,81.07 ; 23.11,18.12 FB1.1 23.11,20.28 ; 43.24,72.18 42.75,72.67 42.26,72.18 ; 33.21,68.59 32.72,68.1 32.22,68.59 ; 8.06,22.11 R44.2 7.08,22.11 ; 39.35,26.49 TEMP1.3 39.35,24.1 ; 40.22,72.18 40.72,72.67 41.21,72.18 ; 7.17,83.96 R5.2 7.17,82.97 ; 39.97,27.35 R39.2 39.97,28.33 ; P2.4 5.3,68.8 ; P2.4 5.3,67.09 ; P2.4 3.59,68.8 ; P2.4 3.59,67.09 ; 34.35,68.59 33.86,68.1 33.37,68.59 ; 35.49,68.59 35,68.1 34.51,68.59 ; 7.17,77.99 R8.2 7.17,77 ; 6.57,25.7 R43.2 7.55,25.7
  TOP w0.508: R9.2 19.43,80.98 ; U4.8 17.42,20.93 C27.1 v1(17.48,21.74) ; R46.2 v1(19,15.01) ; R45.2 v1(19.76,17.04) ; v1(27.89,18.95) C9.1 27.89,21.11 28.5,21.72 U3.8 ; U1.16 v1(13.79,14.25)
  vias: v1(14.94,23.39) v1(14.94,22.38) v1(15.95,24.41) v1(15.95,23.39) v1(15.95,22.38) v1(22.94,15.14) v1(24.08,19.96) v1(24.33,18.69) v1(24.33,17.42) v1(24.33,16.15) v1(25.1,27.97) v1(25.1,27.08) v1(26.11,27.97) v1(26.11,27.08) v1(27.25,27.97) v1(27.25,27.08)
VCC_5V: length 2.5
  TOP w0.635: P2.6 P2.5
I2C2_SCL: length 56.7
  TOP w0.127: 17.98,17.04 16.64,18.39 U4.6 v1(14.3,18.39) ; v1(6.81,54.61) 6.81,53.37 6.25,52.81 6.25,48.23 5.64,47.62 P2.20 ; v1(16.16,25.3) 16.16,26.1 v1(12.9,29.36)
  BOTTOM w0.127: v1(6.81,54.61) 7.82,53.59 7.82,30.25 8.71,29.36 v1(12.9,29.36) ; v1(14.3,18.39) 14.3,24.28 15.32,25.3 v1(16.16,25.3)
I2C2_SDA: length 60.9
  TOP w0.127: P2.19 3.38,49.1 3.38,55.75 3.89,56.26 v1(6.22,56.26) ; v1(13.79,17.12) U4.5 16.64,17.12 17.98,15.77 ; v1(14.05,25.4) 14.05,26.57 v1(12.01,28.6)
  BOTTOM w0.127: v1(14.05,25.4) 13.79,25.15 v1(13.79,17.12) ; v1(6.22,56.26) 6.22,54.33 7.54,53.01 7.54,29.9 8.84,28.6 v1(12.01,28.6)
PR1_ECAP0_IN_PWM0_OUT: length 62.9
  TOP w0.127: J4.1 38.56,20.98 37.67,20.09 v1(37.67,10.44)
  BOTTOM w0.127: P2.42 6.03,18.1 6.03,10.2 13.54,2.69 22.81,2.69 25.1,4.98 27.76,4.98 30.81,8.03 35.26,8.03 v1(37.67,10.44)
PR1_PRU0_GPI5: length 65.5
  TOP w0.127: R30.1 19.43,88.37 v1(19.41,88.39) ; P2.27 3.33,38.89 3.33,45.82 3.89,46.38 5.16,46.38 6.73,47.96 v1(6.73,52.63) ; v1(16.58,77.88) v1(8.84,77.88)
  BOTTOM w0.127: v1(8.84,77.88) 9.35,77.37 9.35,66.88 8.08,65.61 8.08,63.27 5.66,60.86 5.66,53.7 v1(6.73,52.63) ; v1(16.58,77.88) 19.41,80.7 v1(19.41,88.39)
PR1_PRU0_GPI7: length 48.9
  TOP w0.127: P2.25 2.92,41.02 2.92,47.78 3.94,48.79 5.28,48.79 5.92,49.43 5.92,54.74 7.24,56.06 7.24,59.49 6.71,60.02 6.71,71.42 9.09,73.81 11.89,73.81 12.4,73.3 17.22,73.3 18.11,74.19 R28.1
PR1_PRU0_GPI14: length 36.2
  TOP w0.127: TEMP1.2 R39.1 44.78,27.84 45.54,28.6 46.05,28.6 48.08,30.63 48.08,31.9 49.86,33.68 51.46,33.68 P1.30
  BOTTOM w0.127: P1.30 53.82,36.04 53.82,51.59 P1.16
PR1_PRU0_GPI15: length 33.9
  TOP w0.127: P1.15 50.09,52.71 49.1,51.71 49.1,33.43 47.57,31.9 v1(47.57,30.76)
  BOTTOM w0.127: J4.2 45.03,22.76 47.57,25.3 v1(47.57,30.76)
PR1_PRU0_GPO0: length 60.3
  TOP w0.127: v1(7.06,84.99) R12.2 7.01,85.7 Q1.G
  BOTTOM w0.127: P2.31 3.33,33.81 3.33,63.6 3.76,64.03 4.75,64.03 5.94,65.23 7.29,65.23 8.97,66.9 8.97,77.11 7.82,78.26 7.82,84.23 v1(7.06,84.99)
PR1_PRU0_GPO1: length 40.9
  TOP w0.127: R13.2 10.81,67.08 Q2.G v1(7.21,67.16)
  BOTTOM w0.127: P2.29 3.05,36.07 3.05,65.86 3.89,66.7 6.76,66.7 v1(7.21,67.16)
PR1_PRU0_GPO2: length 43.6
  TOP w0.127: Q3.G 11.94,70.59 R14.2 13.03,69.49 13.03,66.45 12.27,65.68 8.33,65.68 7.26,64.62 7.26,60.25 7.8,59.72 7.8,38.28 P2.30
PR1_PRU0_GPO3: length 43.9
  TOP w0.127: P2.28 7.52,40.54 7.52,59.6 6.98,60.14 6.98,65.56 v1(7.66,66.23) ; Q4.G 4.98,73.63 R15.2 5.28,73.69 v1(5.92,74.32)
  BOTTOM w0.127: v1(7.66,66.23) 8.59,67.16 8.59,73.94 8.2,74.32 v1(5.92,74.32)
PR1_PRU1_GPO0: length 43.3
  TOP w0.127: v1(46.69,23.77) v1(44.02,26.44) ; v1(23.06,22.5) 22.01,22.5 U2.8
  BOTTOM w0.127: v1(44.02,26.44) 41.48,28.98 24.21,28.98 23.06,27.84 v1(23.06,22.5) ; v1(46.69,23.77) 47.07,23.39 47.07,17.7 P1.45
PR1_PRU1_GPO1: length 48.1
  TOP w0.127: U2.10 v1(22.94,21.48) ; v1(47.45,23.9) v1(44.02,27.33)
  BOTTOM w0.127: v1(47.45,23.9) 47.45,17.93 49.48,15.9 51.41,15.9 P1.46 ; v1(22.94,21.48) 22.56,21.86 22.56,28.22 23.7,29.36 41.99,29.36 v1(44.02,27.33)
PR1_PRU1_GPO2: length 46.4
  TOP w0.127: v1(20.9,22.38) 21.3,21.98 U2.9 ; v1(45.54,27.84) v1(48.11,25.27)
  BOTTOM w0.127: P1.43 48.74,17.14 48.11,17.78 v1(48.11,25.27) ; v1(45.54,27.84) 43.66,29.72 23.42,29.72 22.17,28.47 22.17,22.89 21.67,22.38 v1(20.9,22.38)
PR1_PRU1_GPO3: length 61.1
  TOP w0.127: v1(41.22,67.84) R18.2 40.41,67.89 Q5.G ; v1(47.32,63.02) v1(47.32,67.08)
  BOTTOM w0.127: v1(47.32,63.02) 47.32,61.09 48.06,60.35 48.06,27.81 49.94,25.93 50.75,25.93 51.26,25.43 51.26,18.59 P1.44 ; v1(41.22,67.84) 41.99,67.08 v1(47.32,67.08)
PR1_PRU1_GPO4: length 54.7
  TOP w0.127: v1(48.84,24.92) 48.84,25.78 48.21,26.42 48.21,30.25 48.46,30.51 48.46,30.91 v1(48.84,31.29) ; v1(44.91,67.72) R19.2 44.09,67.77 Q6.G ; v1(47.83,67.72) v1(47.83,62)
  BOTTOM w0.127: P1.41 50.14,19.69 48.84,20.98 v1(48.84,24.92) ; v1(48.84,31.29) 48.84,60.99 v1(47.83,62) ; v1(44.91,67.72) v1(47.83,67.72)
PR1_PRU1_GPO5: length 60.2
  TOP w0.127: v1(48.34,60.86) 48.34,72.42 48.72,72.8 48.72,74.83 49.35,75.46 R20.2 49.36,75.6 Q7.G
  BOTTOM w0.127: v1(48.34,60.86) 48.34,29.74 49.35,28.73 50.5,28.73 51.64,27.58 51.64,20.73 52.68,19.69 P1.42
PR1_PRU_EDIO_DATA_OUT0: length 43.9
  TOP w0.127: P2.18 5.54,51.26 5.54,54.76 6.68,55.91 v1(6.68,57.3) ; J5.11 35.05,62.1 35.05,64.49 34.43,65.11 34.43,66.51 R35.1
  BOTTOM w0.127: v1(6.68,57.3) 6.76,57.3 8.3,58.84 31.79,58.84 J5.11
PR1_PRU_EDIO_DATA_OUT1: length 45.8
  TOP w0.127: R36.1 33.91,65.89 J5.12 ; v1(6.73,58.8) 6.73,58.24 5.03,56.54 3.53,56.54 3.05,56.06 3.05,51.31 P2.17
  BOTTOM w0.127: J5.12 32.77,62.36 32.77,60.58 31.54,59.35 7.28,59.35 v1(6.73,58.8)
PR1_PRU_EDIO_DATA_OUT2: length 46
  TOP w0.127: J5.13 35.43,61.98 35.43,65 35,65.43 R37.1
  BOTTOM w0.127: J5.13 37.47,60.96 38.56,62.06 42.68,62.06 44.15,63.53 47.45,63.53 48.34,62.64 48.34,62 49.12,61.21 49.12,38.51 P1.27
PR1_PRU_EDIO_DATA_OUT3: length 48.7
  TOP w0.127: R38.1 35.51,66.45 35.51,65.81 36.45,64.87 J5.14
  BOTTOM w0.127: P1.29 51.26,36.02 51.26,61.21 50.88,61.59 49.66,61.59 48.97,62.28 48.97,63.47 48.54,63.91 44.02,63.91 42.47,62.36 38.61,62.36 37.47,63.5 J5.14
PR1_PRU_EDIO_DATA_OUT4: length 55.3
  BOTTOM w0.127: J5.6 26.49,63.7 26.49,65.68 27.13,66.32 45.67,66.32 47.78,64.21 50.85,64.21 51.64,63.42 51.64,38.51 52.68,37.47 P1.28
PR1_PRU_EDIO_DATA_OUT6: length 79.2
  TOP w0.127: P1.39 51.49,23.55 53.39,23.55 53.85,24 53.85,66.45 v1(53.64,66.65)
  BOTTOM w0.127: J5.4 26.95,66.7 45.92,66.7 46.94,65.68 48.46,65.68 49.43,66.65 v1(53.64,66.65)
PR1_UART0_CTS: length 63.5
  TOP w0.127: R51.2 v1(28.91,6.88)
  BOTTOM w0.127: v1(28.91,6.88) 27.25,6.88 26.11,5.74 24.59,5.74 22.3,3.45 13.79,3.45 6.86,10.39 6.86,17.64 7.75,18.53 7.75,27.91 6.05,29.62 6.05,43.48 P2.22
PR1_UART0_RTS: length 68.7
  TOP w0.127: R50.2 v1(27.76,5.99)
  BOTTOM w0.127: v1(27.76,5.99) 27.13,5.36 24.97,5.36 22.68,3.07 13.67,3.07 6.58,10.16 6.58,17.76 7.47,18.65 7.47,27.8 6.67,28.6 1.33,28.6 0.7,29.24 0.7,43.88 P2.21
PR1_UART0_RXD: length 58.8
  TOP w0.127: v1(7.06,42.62) P2.26 ; R49.2 v1(25.48,6.88)
  BOTTOM w0.127: v1(25.48,6.88) 24.21,6.88 21.54,4.22 14.05,4.22 7.7,10.57 7.7,17.3 8.33,17.93 8.33,28.35 7.06,29.62 v1(7.06,42.62)
PR1_UART0_TXD: length 61.4
  TOP w0.127: v1(7.06,43.71) 5.61,43.71 P2.24 ; R48.2 v1(26.62,6.88)
  BOTTOM w0.127: v1(26.62,6.88) 25.98,6.25 24.33,6.25 21.92,3.84 13.92,3.84 7.42,10.34 7.42,17.41 8.05,18.05 8.05,28.12 6.6,29.57 6.6,43.26 v1(7.06,43.71)
SYS_5V: length 2.5
  TOP w0.635: P2.8 P2.7
N10940793: length 13
  TOP w0.127: v1(20.02,5.36) 19.51,5.36 19,4.85 18.62,4.85 18.41,4.65 J1.3 ; U1.14 v1(16.33,10.95)
  BOTTOM w0.127: v1(20.02,5.36) 20.02,7.26 v1(16.33,10.95)
N10940805: length 8.7
  TOP w0.127: J1.7 17.03,4.66 17.6,5.23 18.87,5.23 19.63,5.99 20.78,5.99 21.41,6.63 U1.7
N10940817: length 11.1
  TOP w0.127: v1(16.33,5.99) 16.33,5.36 15.65,4.67 J1.2 ; v1(16.33,9.93) 17.6,11.2 U1.13
  BOTTOM w0.127: v1(16.33,9.93) v1(16.33,5.99)
N10940821: length 7.3
  TOP w0.127: J1.8 19.8,4.6 20.09,4.88 21.06,4.88 22.68,6.5 U1.8
N10940859: length 4.5
  TOP w0.127: C2.1 14.55,9.93 15.06,9.42 U1.2
N10940889: length 6.4
  TOP w0.127: U1.6 20.14,9.55 20.52,9.93 23.06,9.93 C4.1
N10940931: length 2.4
  TOP w0.127: C1.1 13.79,6.76 U1.1
N10940935: length 2.4
  TOP w0.127: C1.2 16.33,6.76 U1.3
N10940955: length 2.1
  TOP w0.127: U1.4 17.73,7.91 C3.1
N10940959: length 2.1
  TOP w0.127: C3.2 18.75,7.91 U1.5
N10941007: length 8.5
  TOP w0.127: R51.1 27.51,10.06 25.73,10.06 24.31,11.48 23.04,11.48 22.68,11.84 U1.9
N10941037: length 9
  TOP w0.127: U1.11 20.14,11.46 20.68,10.92 23.85,10.92 25.48,9.3 25.98,9.3 R48.1
N10941057: length 8.9
  TOP w0.127: U1.10 21.41,11.46 21.67,11.2 24.08,11.2 25.6,9.68 26.75,9.68 R50.1
N10941079: length 9.3
  TOP w0.127: R49.1 23.49,10.64 19.43,10.64 18.87,11.2 U1.12
N10944684: length 3.8
  TOP w0.127: Q1.D 3.2,86.64 1.75,85.18 D1.1
N10944706: length 20.5
  TOP w0.127: D2.1 0.7,80.51 0.7,73.8 v1(2.24,72.26) ; Q2.D 7.7,68.1 7.19,68.61 v1(7.19,70.89)
  BOTTOM w0.127: v1(2.24,72.26) 2.9,72.92 5.16,72.92 v1(7.19,70.89)
N10944710: length 14.6
  TOP w0.127: D3.1 0.98,78.76 0.98,74.05 1.73,73.3 v1(2.24,73.3) ; Q3.D v1(7.44,71.53)
  BOTTOM w0.127: v1(7.44,71.53) 5.66,73.3 v1(2.24,73.3)
N10944714: length 2.9
  TOP w0.127: D4.1 1.74,77.49 Q4.D
N10944926: length 10
  TOP w0.127: R9.1 R30.2 17.87,87.09 SW1.3 SW1.4
N10945010: length 10.7
  TOP w0.127: R28.2 R11.1 17.28,79.47 SW2.3 SW2.4
N10952704: length 9.7
  TOP w0.127: 26.37,24.92 27.25,24.92 27.91,24.26 U3.6 v1(30.94,24.26) ; R27.1 v1(30.3,20.47)
  BOTTOM w0.127: v1(30.3,20.47) 30.94,21.11 v1(30.94,24.26)
N10952708: length 21.1
  TOP w0.127: U3.2 v1(32.84,22.99) ; 33.48,19.71 v1(33.48,20.47) ; R22.1 v1(24.08,26.82)
  BOTTOM w0.127: v1(24.08,26.82) 24.08,27.97 24.78,28.66 31.64,28.66 32.84,27.46 v1(32.84,22.99) 32.84,21.11 v1(33.48,20.47)
N10952712: length 1
  TOP w0.127: C11.2 R22.2
N10952716: length 4.5
  TOP w0.127: U2.2 25.11,21.98 24.84,22.25 24.84,24.16 C11.1
N10952728: length 1.1
  TOP w0.127: R23.2 C12.2
N10952732: length 3.3
  TOP w0.127: 25.22,24.92 25.22,22.76 25.5,22.48 U2.3
N10952860: length 10.5
  TOP w0.127: U3.5 31.22,25.53 32.49,24.26 U3.3 37.01,24.26 R25.2 ; R25.2 C10.2 ; R25.2 R24.1
N10952938: length 10.2
  TOP w0.381: C30.1 v1(28.91,16.83) ; U3.1 32.82,21.72 32.46,21.36 R26.1 v1(32.46,18.95)
  BOTTOM w0.381: v1(28.91,16.83) 31.02,18.95 v1(32.46,18.95)
N10953743: length 17.8
  TOP w0.381: J3.2 46.23,9.73 45.03,8.53 35.89,8.53 34.37,10.06 C31.2
N10962161: length 12.7
  TOP w0.381: U3.7 30.96,22.99 31.32,22.63 R27.2 v1(31.32,18.19) ; C31.1 v1(35.64,16.83)
  BOTTOM w0.381: v1(35.64,16.83) 32.67,16.83 v1(31.32,18.19)
N10987134: length 9.1
  TOP w0.127: U4.1 v1(11.51,20.93) ; R42.1 8.33,23.65 8.84,24.16 SW3.4 v1(11.51,24.16)
  BOTTOM w0.127: v1(11.51,20.93) v1(11.51,24.16)
N10987138: length 13.2
  TOP w0.127: v1(11.51,19.66) U4.2 ; R43.1 8.33,27.2 8.84,26.7 v1(11.38,26.7)
  BOTTOM w0.127: v1(11.51,19.66) 12.01,20.17 12.01,24.28 11.38,24.92 v1(11.38,26.7)
N10987943: length 13.8
  TOP w0.127: R40.1 7.57,17.3 v1(8.33,16.54) ; TP50.1 12.65,16.15 12.65,17.93 14.38,19.66 U4.7
  BOTTOM w0.127: v1(8.33,16.54) 8.33,15.65 9.47,14.5 TP50.1
N10988256: length 4.6
  TOP w0.127: R44.1 8.71,20.6 8.97,20.35 8.97,18.69 9.27,18.39 U4.3
N11005950: length 14.4
  TOP w0.381: C30.2 30.85,12.43 38.49,4.79 J3.3
N11019823: length 11.1
  TOP w0.127: R10.1 v1(40.72,74.45) D5.2 ; D8.1 v1(47.89,76.23)
  BOTTOM w0.127: v1(47.89,76.23) 42.49,76.23 v1(40.72,74.45)
N11021666: length 13.7
  TOP w0.127: D6.1 43.53,77.86 43.69,77.7 43.69,77.06 44.02,76.73 45.34,76.73 46.19,75.88 47.23,75.88 v1(47.89,75.21) D8.3 ; v1(45.92,71.13) 45.92,71.15 45.91,71.13 Q6.D
  BOTTOM w0.127: v1(47.89,75.21) 47.89,73.1 v1(45.92,71.13)
N11021673: length 8.6
  TOP w0.127: D7.1 45.54,77.86 45.93,77.47 D8.2 46.49,78.45 46.69,78.64 50.61,78.64 Q7.D
N11030938: length 17.6
  TOP w0.127: D5.1 40.7,77.86 39.78,76.94 39.78,71.63 v1(40.27,71.13) Q5.D ; D8.4 v1(46.49,75.21)
  BOTTOM w0.127: v1(40.27,71.13) 42.42,71.13 v1(46.49,75.21)
N109444080: length 1.7
  TOP w0.127: D1.2 R5.1
N109444240: length 1.7
  TOP w0.127: D2.2 R6.1
N109444400: length 1.7
  TOP w0.127: D3.2 R7.1
N109444560: length 1.7
  TOP w0.127: R8.1 D4.2
N110315370: length 1.9
  TOP w0.127: D6.2 R16.1
N110319930: length 1.9
  TOP w0.127: D7.2 R17.1

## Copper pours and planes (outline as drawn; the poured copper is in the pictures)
DGND on TOP: 19.96,89.51 19.96,69.01 39.73,69.01 39.73,73.69 48.46,73.69 48.46,78.59 48.59,78.71 52.07,78.71 53.4,78.16 53.95,76.84 53.95,2.54 53.4,1.21 52.07,0.66 23.19,0.66 23.19,14.12 16.08,14.12 16.08,10.19 13.16,10.19 13.16,0.66 2.54,0.66 1.21,1.21 0.66,2.54 0.66,83.82 2.33,87.84 6.35,89.51 ; 6 cut-outs
DGND on BOTTOM: 19.96,89.51 19.96,69.01 39.73,69.01 39.73,78.71 52.07,78.71 53.4,78.16 53.95,76.84 53.95,2.54 53.4,1.21 52.07,0.66 2.54,0.66 1.21,1.21 0.66,2.54 0.66,83.82 2.33,87.84 6.35,89.51 ; 29 cut-outs
VCC_3V3_AUDIO on TOP: 19.13,17.68 20.4,17.68 20.9,18.19 20.9,21.74 19.63,21.74 18.75,20.85 18.75,18.06
VCC_3V3C on TOP: 6.43,25.93 11.89,25.93 13.03,24.79 16.08,24.79 16.59,24.28 16.59,22.38 16.21,22 12.52,22 12.01,21.49 9.22,21.49 8.33,20.6 8.33,19.2 7.82,18.69 6.93,18.69 6.05,19.58 6.05,25.55
VCC_3V3C on TOP: 0.71,66.57 0.71,72.92 4.9,72.92 6.05,74.07 6.05,83.97 6.43,84.35 7.06,84.35 7.57,83.85 7.57,82.07 8.2,81.43 19.38,81.43 19.96,80.85 19.96,69.01 39.7,69.01 39.73,69.04 39.73,72.64 40.26,73.18 46.94,73.18 47.83,72.29 47.83,61.49 49.1,60.22 49.1,32.16 45.16,28.22 40.72,28.22 40.72,24.66 39.83,23.77 38.56,23.77 37.54,24.79 37.54,26.06 36.78,26.06 33.99,28.85 29.67,28.85 27.25,26.44 24.97,26.44 24.08,27.33 24.08,29.74 24.71,30.38 37.54,30.38 38.81,31.65 44.78,31.65 46.81,33.68 46.81,58.83 45.54,60.1 45.54,63.78 42.75,66.57 24.08,66.57 23.19,65.68 23.19,63.53 21.92,62.26 19,62.26 16.71,64.54 16.71,72.67 18.36,74.32 18.36,79.02 17.22,80.16 8.59,80.16 8.2,79.78 8.2,73.3 6.43,71.53 6.43,67.46 5.54,66.57
VCC_3V3C on TOP: 24.59,20.73 24.84,20.47 24.84,15.77 23.83,14.76 22.56,14.76 22.17,15.14 22.17,17.68 21.41,18.44 21.41,20.35 21.79,20.73
VCC_3V3C on BOTTOM: 14.05,13.23 13.41,13.87 13.41,14.63 14.55,15.77 14.55,23.65 15.7,24.79 17.22,24.79 17.98,24.03 17.98,22.12 18.62,21.49 22.56,21.49 23.7,22.63 23.7,27.2 24.84,28.35 27.38,28.35 28.27,27.46 28.27,18.69 22.81,13.23

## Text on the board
BOTTOM: BOTTOM LAYER | 2 | PN#3H0018
Board Geometry/Soldermask Bottom: SOLDERMASK BOTTOM | 2
Ref Des/Silkscreen Bottom: 2 | 45 | 46 | 1 | 3 | 16 | 15 | SILKSCREEN BOTTOM
TOP: TOP LAYER | 1 | 2
Board Geometry/Soldermask Top: 1 | 2
Ref Des/Silkscreen Top: 45 | 46 | WRITE | EEPROM | PROTECT | 1 | 2 | CHARACTER DISPLAY | LCD | ECAP | JUMPER | I2C ADDRESS | RS-232 | OUT | AUDIO | SN#:________ | ASSM PN#:4P0046 | Rev 1.2A | BBB_PRU_CAPE
PAGE_OUTLINE: FABRICATION DRAWING | 1
AST: ASSEMBLY TOP | 1
SMT: SOLDERMASK TOP
User.5: SOLDER PASTE TOP | 1
User.9: SILKSCREEN TOP | 1 | 2
User.13: BOARD NO: 3H0018 | BOARD NAME: | CUSTOMER NAME: | BBB_PRU_CAPE | TEXAS INSTRUMENTS | REV: 1.2A | DESCRIPTION: | DATE: 07/10/14 | SH | OF
User.17: (3X)
User.18: CLASS 2 AND WORKMANSHIP SHALL CONFORM TO | IPC-A-600, CLASS 2. CURRENT REVISIONS. | 2. APPLY LPI SOLDERMASK OVER BARE COPPER (SMOBC), | COLOR: RED SOLDERMASK SHALL | CONFORM TO IPC-SM-840, CLASS H. CURRENT REV. | 3. SOLDERMASK ARTWORK HAS ZERO (0) OVERSIZED PADS. | FABRICATION VENDOR IS ALLOWED TO ADJUST THE COMPONENT | SOLDERMASK PADS TO MEET THEIR TOOLING REQUIREMENTS. | 4. APPLY LPI SILKSCREEN OR EQUIVALENT PER THE ARTWORK. | IMMERSION GOLD, NICKEL 150 MICROINCHES THK MIN | GOLD 5-15 MICROINCHES THK MIN. | 2. THE PWB SHALL BE FABRICATED TO IPC-6012, | 3. BOARD MATERIAL SHALL BE 180 Tg/350 Td ISOLA FR-370 HR | OR EQUIVALENT, RoHS COMPLIANT AND LEAD FREE | ASSEMBLY CAPABLE.  BOARD MATERIAL SHALL | MEET OR EXCEED IPC-4101B. COLOR: NATURAL. | 4. BOARD MATERIAL & CONSTRUCTION TO BE UL94V0 | CERTIFIED AND MARKED ON THE FINISHED BOARD. | 5. MINIMUM COPPER WALL THICKNESS OF PLATED-THRU | HOLES TO BE .001 INCH, WITH A MINIMUM | ANNULAR RING OF .002 INCH. | COLOR: WHITE. | FAB NOTES: | 6. OVERALL BOARD THICKNESS TO BE .0625 +/- 10% | AND APPLIES AFTER ALL LAMINATION AND PLATING | PROCESS NOTES: | 1. PLATE ALL EXPOSED AREAS WITH ELECTROLESS | 1. ALL DIMENSIONS ARE IN INCHES, UNLESS | OTHERWISE NOTED. | SUPPLIED IPC-D-356 NETLIST. | PROCESSES, MEASURED FROM COPPER TO COPPER. | 8. BOARD MUST BE ELECTRICALLY TESTED USING | 9. ALL VIAS TO HAVE SOLDERMASK. | 7. MAX. WARP & TWIST TO BE .0075 INCHES PER INCH.
User.19: FIGURE | SIZE | 10.0 | 35.43 | 40.0 | 120.0 | 59.0 | 67.0 | DRILL CHART: TOP to BOTTOM | ALL UNITS ARE IN MILS | TOLERANCE | +3.0/-3.0 | +3.15/-3.15 | +5.0/-5.0 | +0.0/-0.0 | PLATED | NON-PLATED | QTY | 246 | 3 | 108 | 153 | 2
